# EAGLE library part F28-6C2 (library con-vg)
CONNECTOR female, 28 pins + 6 coax, type C
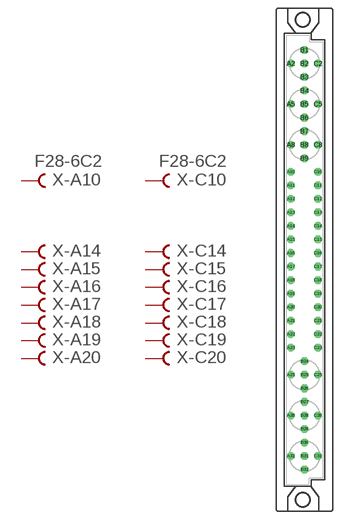
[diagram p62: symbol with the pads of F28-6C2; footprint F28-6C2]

Designator prefix X; gates -A10=FVAL -A14=FEM -A15=FEM -A16=FEM -A17=FEM -A18=FEM -A19=FEM -A20=FEM -C10=FVAL -C14=FEM -C15=FEM -C16=FEM -C17=FEM -C18=FEM -C19=FEM -C20=FEM -A21=FEM -A22=FEM -A23=FEM -C21=FEM -C22=FEM -C23=FEM -A11=FEM -A12=FEM -A13=FEM -C11=FEM -C12=FEM -C13=FEM -1=COAX -2=COAX -3=COAX -4=COAX -5=COAX -6=COAX

## F28-6C2  [F28-6C2]
A2  -1:S3  pas
A5  -2:S3  pas
A8  -3:S3  pas
A10  -A10:B  pas
A11  -A11:B  pas
A12  -A12:B  pas
A13  -A13:B  pas
A14  -A14:B  pas
A15  -A15:B  pas
A16  -A16:B  pas
A17  -A17:B  pas
A18  -A18:B  pas
A19  -A19:B  pas
A20  -A20:B  pas
A21  -A21:B  pas
A22  -A22:B  pas
A23  -A23:B  pas
A25  -4:S3  pas
A28  -5:S3  pas
A31  -6:S3  pas
B1  -1:S1  pas
B2  -1:S  pas
B3  -1:S2  pas
B4  -2:S1  pas
B5  -2:S  pas
B6  -2:S2  pas
B7  -3:S1  pas
B8  -3:S  pas
B9  -3:S2  pas
B24  -4:S1  pas
B25  -4:S  pas
B26  -4:S2  pas
B27  -5:S1  pas
B28  -5:S  pas
B29  -5:S2  pas
B30  -6:S1  pas
B31  -6:S  pas
B32  -6:S2  pas
C2  -1:S4  pas
C5  -2:S4  pas
C8  -3:S4  pas
C10  -C10:B  pas
C11  -C11:B  pas
C12  -C12:B  pas
C13  -C13:B  pas
C14  -C14:B  pas
C15  -C15:B  pas
C16  -C16:B  pas
C17  -C17:B  pas
C18  -C18:B  pas
C19  -C19:B  pas
C20  -C20:B  pas
C21  -C21:B  pas
C22  -C22:B  pas
C23  -C23:B  pas
C25  -4:S4  pas
C28  -5:S4  pas
C31  -6:S4  pas

## Footprint F28-6C2 (pad centres in mm)
CONNECTOR female, 28 pins + 6 coax, type C
drill 0.914 octagon: A2 -2.54,36.83; A5 -2.54,29.21; A8 -2.54,21.59; A10 -2.54,16.51; A11 -2.54,13.97; A12 -2.54,11.43; A13 -2.54,8.89; A14 -2.54,6.35; A15 -2.54,3.81; A16 -2.54,1.27; A17 -2.54,-1.27; A18 -2.54,-3.81; A19 -2.54,-6.35; A20 -2.54,-8.89; A21 -2.54,-11.43; A22 -2.54,-13.97; A23 -2.54,-16.51; A25 -2.54,-21.59; A28 -2.54,-29.21; A31 -2.54,-36.83; B1 0,39.37; B2 0,36.83; B3 0,34.29; B4 0,31.75; B5 0,29.21; B6 0,26.67; B7 0,24.13; B8 0,21.59; B9 0,19.05; B24 0,-19.05; B25 0,-21.59; B26 0,-24.13; B27 0,-26.67; B28 0,-29.21; B29 0,-31.75; B30 0,-34.29; B31 0,-36.83; B32 0,-39.37; C2 2.54,36.83; C5 2.54,29.21; C8 2.54,21.59; C10 2.54,16.51; C11 2.54,13.97; C12 2.54,11.43; C13 2.54,8.89; C14 2.54,6.35; C15 2.54,3.81; C16 2.54,1.27; C17 2.54,-1.27; C18 2.54,-3.81; C19 2.54,-6.35; C20 2.54,-8.89; C21 2.54,-11.43; C22 2.54,-13.97; C23 2.54,-16.51; C25 2.54,-21.59; C28 2.54,-29.21; C31 2.54,-36.83
hole 2.794 at -0.305,45.009
hole 2.794 at -0.305,-45.009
